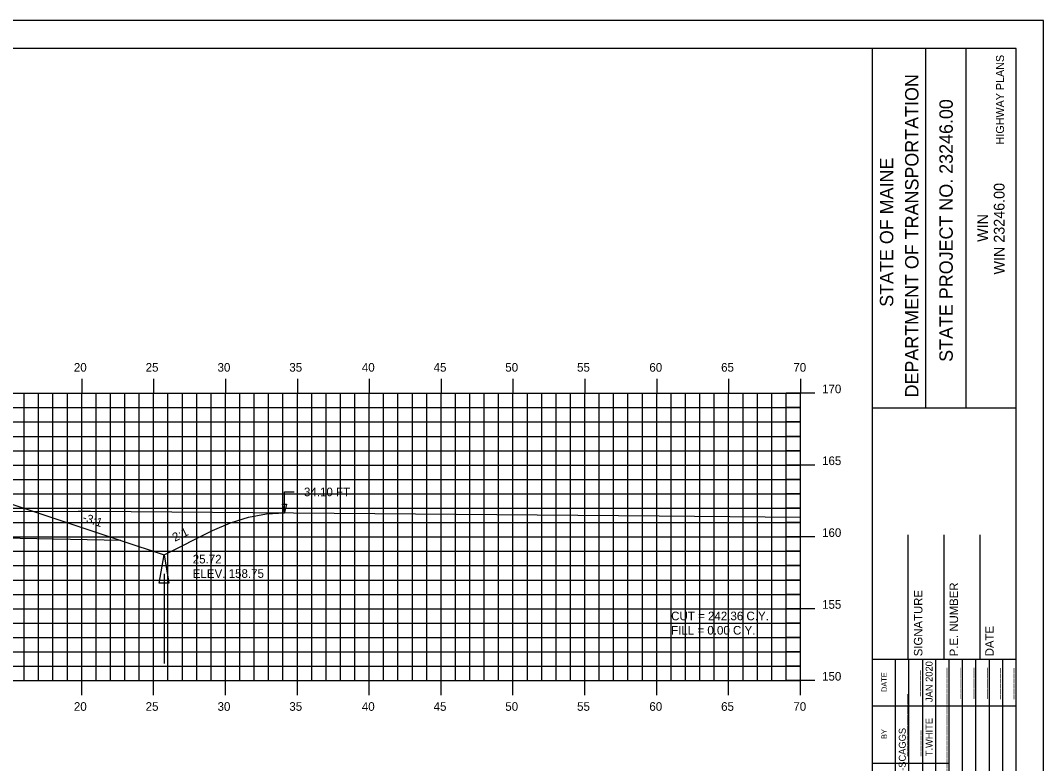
# Model space of a CAD drawing. Extents: x 1142976 to 1143146, y 608981 to 609091.
# Drawn here: x 1143075.3 to 1143146.5, y 609039.6 to 609091.3 of the extents above; entities that cross this region are included whole.
import ezdxf

# ---------------------------------------------------------------- set-up
doc = ezdxf.new("R2010")
doc.units = 0
for name, color, linetype in [('ANNOTATION', 7, 'Continuous'), ('BORDER', 7, 'Continuous'), ('D_Drainage_Ditch_Line', 7, 'Continuous'), ('D_Roadway_SlopeLines', 7, 'Continuous'), ('D_Roadway_SubGrade', 7, 'Continuous'), ('D_Text_Standard', 7, 'Continuous'), ('H_V ANNOTATION', 7, 'Continuous'), ('HIGHWAY_TITLE', 7, 'Continuous'), ('MAJOR', 7, 'Continuous'), ('MINOR', 7, 'Continuous'), ('PLOT BOUNDARY', 7, 'Continuous'), ('S_Roadway_Centerline', 7, 'Continuous')]:
    doc.layers.add(name, color=color, linetype=linetype)

msp = doc.modelspace()

# ---------------------------------------------------------------- linework, layer by layer
msp.add_lwpolyline([(1143024.106, 609057.813), (1143025.356, 609057.688), (1143026.606, 609057.421), (1143027.856, 609057.01), (1143029.106, 609056.457), (1143033.842, 609054.089), (1143036.842, 609055.089), (1143044.566, 609057.664), (1143044.567, 609057.664), (1143048.567, 609057.824), (1143059.567, 609058.044), (1143070.567, 609057.824), (1143074.567, 609057.664), (1143082.29, 609055.089), (1143085.29, 609054.089), (1143088.668, 609055.778), (1143089.918, 609056.324), (1143091.168, 609056.71), (1143092.418, 609056.938), (1143093.668, 609057.008)])
at = {"layer": 'BORDER'}
for p, q in [((1143134.567, 608984.335), (1143134.567, 609089.335)), ((1143138.295, 609064.332), (1143138.295, 609089.332)), ((1143141.09, 609064.332), (1143141.09, 609089.332)), ((1143134.568, 609064.329), (1143144.567, 609064.329)), ((1143137.067, 609046.838), (1143137.067, 609055.485)), ((1143139.567, 609046.838), (1143139.567, 609055.485)), ((1143142.067, 609046.838), (1143142.067, 609055.485)), ((1143134.567, 609046.838), (1143144.567, 609046.838))]:
    msp.add_line(p, q, dxfattribs=at)
msp.add_lwpolyline([(1142984.567, 608984.335), (1143144.567, 608984.335), (1143144.567, 609089.335), (1142984.567, 609089.335)], close=True, dxfattribs=at)
for points in [[(1143136.182, 609043.588), (1143136.182, 609046.838)], [(1143137.114, 609029.341), (1143137.114, 609046.838)], [(1143138.046, 609046.838), (1143138.046, 609029.341)], [(1143138.978, 609029.341), (1143138.978, 609046.838)], [(1143139.909, 609029.341), (1143139.909, 609046.838)], [(1143140.841, 609029.341), (1143140.841, 609046.838)], [(1143141.773, 609029.341), (1143141.773, 609046.838)], [(1143142.704, 609029.341), (1143142.704, 609046.838)], [(1143143.636, 609029.341), (1143143.636, 609046.838)], [(1143136.182, 609029.341), (1143136.182, 609046.132)], [(1143134.567, 609043.588), (1143144.567, 609043.588)], [(1143134.567, 609039.588), (1143136.182, 609039.588)], [(1143136.182, 609039.588), (1143139.908, 609039.588)]]:
    msp.add_lwpolyline(points, dxfattribs=at)
at = {"layer": 'D_Drainage_Ditch_Line'}
msp.add_line((1143085.29, 609052.777), (1143085.29, 609046.533), dxfattribs=at)
msp.add_lwpolyline([(1143085.618, 609052.121), (1143084.962, 609052.121), (1143085.29, 609054.089)], close=True, dxfattribs=at)
at = {"layer": 'D_Roadway_SlopeLines'}
for points in [[(1143085.29, 609054.089), (1143088.668, 609055.778), (1143089.918, 609056.324), (1143091.168, 609056.71), (1143092.418, 609056.938), (1143093.668, 609057.008)], [(1143082.29, 609055.089), (1143085.29, 609054.089)]]:
    msp.add_lwpolyline(points, dxfattribs=at)
at = {"layer": 'D_Roadway_SubGrade'}
msp.add_lwpolyline([(1143070.567, 609057.407), (1143070.567, 609057.574), (1143074.567, 609057.414), (1143074.567, 609057.664), (1143074.567, 609057.664), (1143082.29, 609055.089), (1143070.567, 609055.324)], close=True, dxfattribs=at)
at = {"layer": 'D_Text_Standard'}
msp.add_lwpolyline([(1143093.668, 609057.028), (1143093.666, 609058.466), (1143094.346, 609058.466)], dxfattribs=at)
msp.add_lwpolyline([(1143093.668, 609057.028), (1143093.522, 609057.61), (1143093.813, 609057.61)], close=True, dxfattribs=at)
at = {"layer": 'MAJOR'}
for p, q in [((1143079.567, 609066.337), (1143079.567, 609065.335)), ((1143084.567, 609066.337), (1143084.567, 609065.335)), ((1143089.567, 609066.337), (1143089.567, 609065.335)), ((1143094.567, 609066.337), (1143094.567, 609065.335)), ((1143099.567, 609066.337), (1143099.567, 609065.335)), ((1143104.567, 609066.337), (1143104.567, 609065.335)), ((1143109.567, 609066.337), (1143109.567, 609065.335)), ((1143114.567, 609066.337), (1143114.567, 609065.335)), ((1143119.567, 609066.337), (1143119.567, 609065.335)), ((1143124.567, 609066.337), (1143124.567, 609065.335)), ((1143129.567, 609066.337), (1143129.567, 609065.335)), ((1142989.567, 609065.335), (1143129.567, 609065.335)), ((1142989.567, 609065.335), (1143129.567, 609065.335)), ((1143079.567, 609045.335), (1143079.567, 609065.335)), ((1143084.567, 609045.335), (1143084.567, 609065.335)), ((1143089.567, 609045.335), (1143089.567, 609065.335)), ((1143094.567, 609045.335), (1143094.567, 609065.335)), ((1143099.567, 609045.335), (1143099.567, 609065.335)), ((1143104.567, 609045.335), (1143104.567, 609065.335)), ((1143109.567, 609045.335), (1143109.567, 609065.335)), ((1143114.567, 609045.335), (1143114.567, 609065.335)), ((1143119.567, 609045.335), (1143119.567, 609065.335)), ((1143124.567, 609045.335), (1143124.567, 609065.335)), ((1143130.569, 609065.335), (1143128.565, 609065.335)), ((1143129.567, 609045.335), (1143129.567, 609065.335)), ((1143129.567, 609045.335), (1143129.567, 609065.335)), ((1142989.567, 609060.335), (1143129.567, 609060.335)), ((1143130.569, 609060.335), (1143128.565, 609060.335)), ((1142989.567, 609055.335), (1143129.567, 609055.335)), ((1143130.569, 609055.335), (1143128.565, 609055.335)), ((1142989.567, 609050.335), (1143129.567, 609050.335)), ((1143130.569, 609050.335), (1143128.565, 609050.335)), ((1142989.567, 609045.335), (1143129.567, 609045.335)), ((1142989.567, 609045.335), (1143129.567, 609045.335)), ((1143079.567, 609044.333), (1143079.567, 609045.335)), ((1143084.567, 609044.333), (1143084.567, 609045.335)), ((1143089.567, 609044.333), (1143089.567, 609045.335)), ((1143094.567, 609044.333), (1143094.567, 609045.335)), ((1143099.567, 609044.333), (1143099.567, 609045.335)), ((1143104.567, 609044.333), (1143104.567, 609045.335)), ((1143109.567, 609044.333), (1143109.567, 609045.335)), ((1143114.567, 609044.333), (1143114.567, 609045.335)), ((1143119.567, 609044.333), (1143119.567, 609045.335)), ((1143124.567, 609044.333), (1143124.567, 609045.335)), ((1143130.569, 609045.335), (1143128.565, 609045.335)), ((1143129.567, 609044.333), (1143129.567, 609045.335))]:
    msp.add_line(p, q, dxfattribs=at)
at = {"layer": 'MINOR'}
for p, q in [((1143075.567, 609045.335), (1143075.567, 609065.335)), ((1143076.567, 609045.335), (1143076.567, 609065.335)), ((1143077.567, 609045.335), (1143077.567, 609065.335)), ((1143078.567, 609045.335), (1143078.567, 609065.335)), ((1143080.567, 609045.335), (1143080.567, 609065.335)), ((1143081.567, 609045.335), (1143081.567, 609065.335)), ((1143082.567, 609045.335), (1143082.567, 609065.335)), ((1143083.567, 609045.335), (1143083.567, 609065.335)), ((1143085.567, 609045.335), (1143085.567, 609065.335)), ((1143086.567, 609045.335), (1143086.567, 609065.335)), ((1143087.567, 609045.335), (1143087.567, 609065.335)), ((1143088.567, 609045.335), (1143088.567, 609065.335)), ((1143090.567, 609045.335), (1143090.567, 609065.335)), ((1143091.567, 609045.335), (1143091.567, 609065.335)), ((1143092.567, 609045.335), (1143092.567, 609065.335)), ((1143093.567, 609045.335), (1143093.567, 609065.335)), ((1143095.567, 609045.335), (1143095.567, 609065.335)), ((1143096.567, 609045.335), (1143096.567, 609065.335)), ((1143097.567, 609045.335), (1143097.567, 609065.335)), ((1143098.567, 609045.335), (1143098.567, 609065.335)), ((1143100.567, 609045.335), (1143100.567, 609065.335)), ((1143101.567, 609045.335), (1143101.567, 609065.335)), ((1143102.567, 609045.335), (1143102.567, 609065.335)), ((1143103.567, 609045.335), (1143103.567, 609065.335)), ((1143105.567, 609045.335), (1143105.567, 609065.335)), ((1143106.567, 609045.335), (1143106.567, 609065.335)), ((1143107.567, 609045.335), (1143107.567, 609065.335)), ((1143108.567, 609045.335), (1143108.567, 609065.335)), ((1143110.567, 609045.335), (1143110.567, 609065.335)), ((1143111.567, 609045.335), (1143111.567, 609065.335)), ((1143112.567, 609045.335), (1143112.567, 609065.335)), ((1143113.567, 609045.335), (1143113.567, 609065.335)), ((1143115.567, 609045.335), (1143115.567, 609065.335)), ((1143116.567, 609045.335), (1143116.567, 609065.335)), ((1143117.567, 609045.335), (1143117.567, 609065.335)), ((1143118.567, 609045.335), (1143118.567, 609065.335)), ((1143120.567, 609045.335), (1143120.567, 609065.335)), ((1143121.567, 609045.335), (1143121.567, 609065.335)), ((1143122.567, 609045.335), (1143122.567, 609065.335)), ((1143123.567, 609045.335), (1143123.567, 609065.335)), ((1143125.567, 609045.335), (1143125.567, 609065.335)), ((1143126.567, 609045.335), (1143126.567, 609065.335)), ((1143127.567, 609045.335), (1143127.567, 609065.335)), ((1143128.567, 609045.335), (1143128.567, 609065.335)), ((1142989.567, 609064.335), (1143129.567, 609064.335)), ((1143129.567, 609064.335), (1143128.565, 609064.335)), ((1142989.567, 609063.335), (1143129.567, 609063.335)), ((1143129.567, 609063.335), (1143128.565, 609063.335)), ((1142989.567, 609062.335), (1143129.567, 609062.335)), ((1143129.567, 609062.335), (1143128.565, 609062.335)), ((1142989.567, 609061.335), (1143129.567, 609061.335)), ((1143129.567, 609061.335), (1143128.565, 609061.335)), ((1142989.567, 609059.335), (1143129.567, 609059.335)), ((1143129.567, 609059.335), (1143128.565, 609059.335)), ((1142989.567, 609058.335), (1143129.567, 609058.335)), ((1143129.567, 609058.335), (1143128.565, 609058.335)), ((1142989.567, 609057.335), (1143129.567, 609057.335)), ((1143129.567, 609057.335), (1143128.565, 609057.335)), ((1142989.567, 609056.335), (1143129.567, 609056.335)), ((1143129.567, 609056.335), (1143128.565, 609056.335)), ((1142989.567, 609054.335), (1143129.567, 609054.335)), ((1143129.567, 609054.335), (1143128.565, 609054.335)), ((1142989.567, 609053.335), (1143129.567, 609053.335)), ((1143129.567, 609053.335), (1143128.565, 609053.335)), ((1142989.567, 609052.335), (1143129.567, 609052.335)), ((1143129.567, 609052.335), (1143128.565, 609052.335)), ((1142989.567, 609051.335), (1143129.567, 609051.335)), ((1143129.567, 609051.335), (1143128.565, 609051.335)), ((1142989.567, 609049.335), (1143129.567, 609049.335)), ((1143129.567, 609049.335), (1143128.565, 609049.335)), ((1142989.567, 609048.335), (1143129.567, 609048.335)), ((1143129.567, 609048.335), (1143128.565, 609048.335)), ((1142989.567, 609047.335), (1143129.567, 609047.335)), ((1143129.567, 609047.335), (1143128.565, 609047.335)), ((1142989.567, 609046.335), (1143129.567, 609046.335)), ((1143129.567, 609046.335), (1143128.565, 609046.335))]:
    msp.add_line(p, q, dxfattribs=at)
at = {"layer": 'PLOT BOUNDARY'}
msp.add_lwpolyline([(1142976.473, 608981.276), (1143146.473, 608981.276), (1143146.473, 609091.276), (1142976.473, 609091.276)], close=True, dxfattribs=at)
at = {"layer": 'S_Roadway_Centerline'}
msp.add_lwpolyline([(1142989.567, 609057.515), (1143000.793, 609057.983), (1143008.234, 609058.403), (1143010.248, 609058.4), (1143030.364, 609057.548), (1143034.453, 609057.089), (1143036.075, 609056.784), (1143038.74, 609057.457), (1143039.603, 609057.77), (1143040.548, 609057.805), (1143042.591, 609058.025), (1143045.569, 609058.133), (1143054.031, 609058.462), (1143062.329, 609058.395), (1143065.441, 609058.42), (1143066.331, 609058.333), (1143068.826, 609058.103), (1143072.162, 609057.402), (1143073.276, 609057.103), (1143079.308, 609057.124), (1143079.395, 609057.13), (1143080.178, 609057.118), (1143119.741, 609056.795), (1143129.567, 609056.713)], dxfattribs=at)

# ---------------------------------------------------------------- texts
at = {"layer": 'ANNOTATION'}
for s, rotation, p in [('-3:1', 341.56521, (1143079.578, 609056.447)), ('2:1', 26.56505, (1143086.051, 609054.988))]:
    msp.add_text(s, height=0.6, rotation=rotation, dxfattribs=at).set_placement(p)
at = {"layer": 'BORDER'}
for s, height, p in [('DEPARTMENT OF TRANSPORTATION', 0.93176, (1143137.774, 609065.041)), ('STATE PROJECT NO. 23246.00', 0.93176, (1143140.159, 609067.517)), ('STATE OF MAINE', 0.93176, (1143136.022, 609071.347)), ('WIN 23246.00', 0.74527, (1143143.762, 609073.596)), ('WIN', 0.7453, (1143142.603, 609075.865)), ('P.E. NUMBER', 0.59055, (1143140.527, 609047.03)), ('SIGNATURE', 0.5906, (1143138.047, 609047.03)), ('DATE', 0.5906, (1143143.008, 609047.03)), ('JAN 2020', 0.4845, (1143138.753, 609043.843)), ('DATE', 0.3714, (1143135.571, 609044.544)), ('_____', 0.4845, (1143137.784, 609044.243)), ('______', 0.4845, (1143139.647, 609044.063)), ('______', 0.4845, (1143140.579, 609044.065)), ('______', 0.4845, (1143141.511, 609044.067)), ('______', 0.4845, (1143142.442, 609044.067)), ('______', 0.4845, (1143143.374, 609044.036)), ('______', 0.4845, (1143144.306, 609044.036)), ('____________', 0.48455, (1143136.89, 609040.073)), ('____________', 0.48455, (1143139.647, 609040.073)), ('T.WHITE', 0.4845, (1143138.753, 609040.073)), ('M YOUNG-SCAGGS', 0.48455, (1143136.89, 609035.961)), ('BY', 0.3714, (1143135.571, 609041.273)), ('_____', 0.4845, (1143137.821, 609040.073)), ('____________', 0.48455, (1143139.647, 609035.961))]:
    msp.add_text(s, height=height, rotation=90, dxfattribs=at).set_placement(p)
at = {"layer": 'D_Text_Standard'}
for s, p in [('34.10 FT', (1143095.026, 609058.166)), ('25.72', (1143087.29, 609053.489)), ('ELEV. 158.75', (1143087.29, 609052.487)), ('CUT = 242.36 C.Y.', (1143120.567, 609049.535)), ('FILL = 0.00 C.Y.', (1143120.567, 609048.539))]:
    msp.add_text(s, height=0.6, dxfattribs=at).set_placement(p)
at = {"layer": 'H_V ANNOTATION'}
for s, p in [('20', (1143079.021, 609066.835)), ('25', (1143084.012, 609066.835)), ('30', (1143089.015, 609066.835)), ('35', (1143094.007, 609066.835)), ('40', (1143099.053, 609066.835)), ('45', (1143104.045, 609066.835)), ('50', (1143109.031, 609066.835)), ('55', (1143114.023, 609066.835)), ('60', (1143119.053, 609066.835)), ('65', (1143124.045, 609066.835)), ('70', (1143129.069, 609066.835)), ('170', (1143131.067, 609065.335)), ('165', (1143131.067, 609060.335)), ('160', (1143131.067, 609055.335)), ('155', (1143131.067, 609050.335)), ('150', (1143131.067, 609045.335)), ('20', (1143079.021, 609043.235)), ('25', (1143084.012, 609043.235)), ('30', (1143089.015, 609043.235)), ('35', (1143094.007, 609043.235)), ('40', (1143099.053, 609043.235)), ('45', (1143104.045, 609043.235)), ('50', (1143109.031, 609043.235)), ('55', (1143114.023, 609043.235)), ('60', (1143119.053, 609043.235)), ('65', (1143124.045, 609043.235)), ('70', (1143129.069, 609043.235))]:
    msp.add_text(s, height=0.6, dxfattribs=at).set_placement(p)
at = {"layer": 'HIGHWAY_TITLE'}
msp.add_text('HIGHWAY PLANS', height=0.55901, rotation=90, dxfattribs=at).set_placement((1143143.725, 609082.65))

doc.saveas('drawing.dxf')
